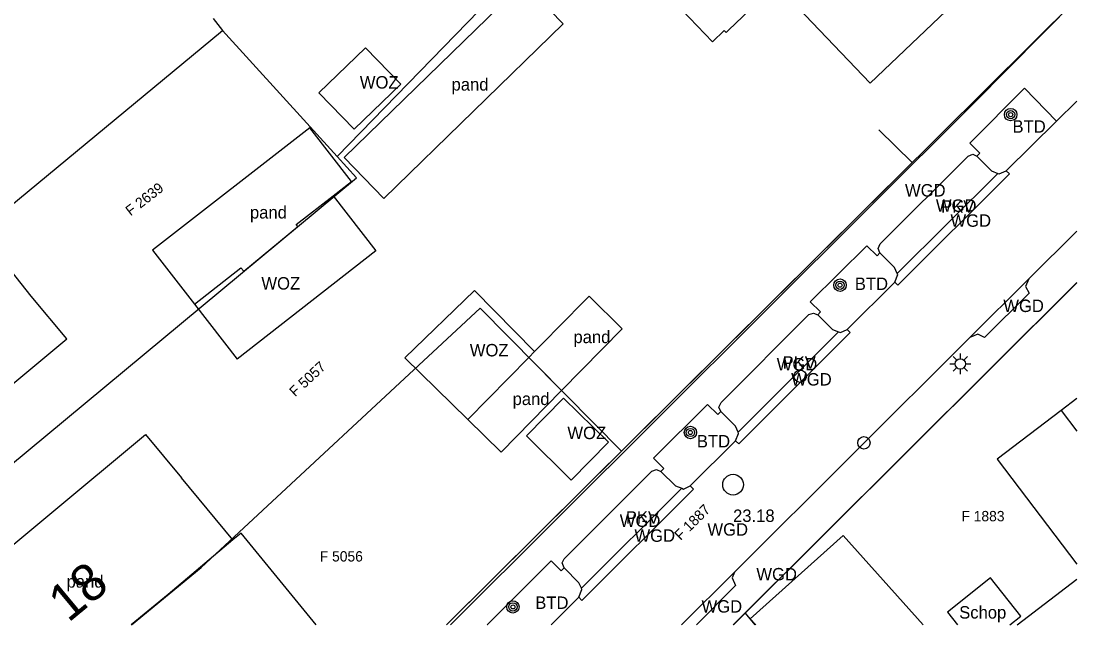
# Model space of a CAD drawing. Extents: x 198240 to 198429, y 356553 to 356721.
# Drawn here: x 198378.2 to 198429.3, y 356553.7 to 356582.9 of the extents above; entities that cross this region are included whole.
import ezdxf

# ---------------------------------------------------------------- set-up
doc = ezdxf.new("R2010")
doc.units = 0
for name, color, linetype in [('begroeid terreindeel kenmerkpunt', 7, 'Continuous'), ('bijgebouw', 7, 'Continuous'), ('BOOM', 7, 'Continuous'), ('Grens maaiveld', 7, 'Continuous'), ('grens WOZ object', 7, 'Continuous'), ('hoofdgebouw', 7, 'Continuous'), ('Hoogtepunt', 7, 'Continuous'), ('huisnummerreeks BGT', 7, 'Continuous'), ('identificerend kenmerkpunt bijpand', 7, 'Continuous'), ('identificerend kenmerkpunt pand', 7, 'Continuous'), ('identificerend kenmerkpunt parkeervak', 7, 'Continuous'), ('identificerend kenmerkpunt WOZ object', 7, 'Continuous'), ('Inspectieput_rioolput', 7, 'Continuous'), ('kant verharding', 7, 'Continuous'), ('kolk', 7, 'Continuous'), ('LICHTMAST', 7, 'Continuous'), ('Perceelnummer', 7, 'Continuous'), ('perceelsgrens_definitief', 7, 'Continuous'), ('schutting geen IMGeo', 7, 'Continuous'), ('tussenmuur', 7, 'Continuous'), ('tussenmuur bijgebouw (GBKN Zuid)', 7, 'Continuous'), ('wegdeel kenmerkpunt', 7, 'Continuous'), ('weginrichtingselement lijn', 7, 'Continuous')]:
    doc.layers.add(name, color=color, linetype=linetype)

msp = doc.modelspace()

# ---------------------------------------------------------------- linework, layer by layer
at = {"layer": 'bijgebouw'}
for p, q in [((198395.764, 356574.305), (198404.433, 356582.738)), ((198395.764, 356574.305), (198393.844, 356576.278)), ((198388.999, 356570.783), (198391.604, 356572.945)), ((198403.387, 356567.24), (198405.417, 356569.305)), ((198403.054, 356566.902), (198402.775, 356566.618)), ((198403.387, 356567.24), (198403.054, 356566.902)), ((198402.775, 356566.618), (198399.823, 356563.617)), ((198429.251, 356564.637), (198428.489, 356564.058)), ((198413.472, 356553.991), (198413.732, 356553.702))]:
    msp.add_line(p, q, dxfattribs=at)
for points in [[(198404.433, 356582.738), (198402.513, 356584.711), (198393.844, 356576.278)], [(198393.313, 356574.422), (198394.212, 356575.122), (198392.188, 356577.719), (198384.587, 356571.795), (198386.611, 356569.198)], [(198391.604, 356572.945), (198391.534, 356573.035), (198393.313, 356574.422)], [(198386.611, 356569.198), (198388.865, 356570.955), (198388.999, 356570.783)], [(198404.358, 356565.019), (198407.286, 356567.997), (198405.682, 356569.574), (198405.417, 356569.305)], [(198399.823, 356563.617), (198401.428, 356562.039), (198404.358, 356565.019)], [(198413.472, 356553.991), (198417.952, 356558.012), (198421.83, 356553.702)]]:
    msp.add_lwpolyline(points, dxfattribs=at)
at = {"layer": 'BOOM'}
for centre, radius in [((198426.05, 356578.35), 0.3), ((198426.05, 356578.35), 0.2), ((198426.05, 356578.35), 0.1), ((198417.807, 356570.11), 0.3), ((198417.807, 356570.11), 0.2), ((198417.807, 356570.11), 0.1), ((198410.579, 356562.994), 0.3), ((198410.579, 356562.994), 0.2), ((198410.579, 356562.994), 0.1), ((198402.003, 356554.569), 0.3), ((198402.003, 356554.569), 0.2), ((198402.003, 356554.569), 0.1)]:
    msp.add_circle(centre, radius, dxfattribs=at)
at = {"layer": 'Grens maaiveld'}
for points in [[(198425.837, 356575.632), (198425.998, 356575.484), (198420.594, 356570.105), (198420.453, 356570.259)], [(198418.147, 356567.967), (198418.298, 356567.827), (198412.917, 356562.449), (198412.763, 356562.594)], [(198410.57, 356560.418), (198410.729, 356560.263), (198405.339, 356554.884), (198405.183, 356555.039)]]:
    msp.add_lwpolyline(points, dxfattribs=at)
at = {"layer": 'grens WOZ object'}
for p, q in [((198412.437, 356582.444), (198414.721, 356584.63)), ((198412.308, 356582.321), (198412.437, 356582.444)), ((198392.632, 356579.397), (198394.874, 356581.576)), ((198394.874, 356581.576), (198396.58, 356579.821)), ((198396.58, 356579.821), (198394.337, 356577.642)), ((198394.337, 356577.642), (198392.632, 356579.397)), ((198393.313, 356574.422), (198395.384, 356571.765)), ((198395.384, 356571.765), (198388.682, 356566.541)), ((198386.611, 356569.198), (198388.682, 356566.541)), ((198402.654, 356562.826), (198404.448, 356564.652)), ((198404.448, 356564.652), (198406.615, 356562.525)), ((198428.489, 356564.058), (198425.397, 356561.71)), ((198404.821, 356560.698), (198402.654, 356562.826)), ((198406.615, 356562.525), (198404.821, 356560.698)), ((198425.397, 356561.71), (198429.251, 356556.635)), ((198425.07, 356555.97), (198422.994, 356554.321)), ((198426.541, 356554.119), (198425.07, 356555.97)), ((198422.994, 356554.321), (198423.486, 356553.702)), ((198426.015, 356553.702), (198426.541, 356554.119))]:
    msp.add_line(p, q, dxfattribs=at)
for points in [[(198409.054, 356584.582), (198411.65, 356581.864), (198412.216, 356582.419), (198412.308, 356582.321)], [(198399.823, 356563.617), (198396.784, 356566.605), (198400.147, 356569.847), (198403.054, 356566.902)]]:
    msp.add_lwpolyline(points, dxfattribs=at)
at = {"layer": 'hoofdgebouw'}
for p, q in [((198378.73, 356569.587), (198376.341, 356572.579)), ((198428.489, 356564.058), (198429.251, 356563.054)), ((198388.477, 356557.806), (198385.996, 356560.798)), ((198388.866, 356558.133), (198388.477, 356557.806)), ((198392.493, 356553.702), (198388.866, 356558.133))]:
    msp.add_line(p, q, dxfattribs=at)
for points in [[(198414.721, 356584.63), (198419.264, 356579.863), (198424.933, 356585.283), (198420.379, 356590.045)], [(198366.989, 356565.052), (198371.275, 356559.894), (198380.45, 356567.516), (198378.73, 356569.587)], [(198376.395, 356553.702), (198375.087, 356555.277), (198384.259, 356562.891), (198385.996, 356560.798)]]:
    msp.add_lwpolyline(points, dxfattribs=at)
at = {"layer": 'Inspectieput_rioolput'}
msp.add_circle((198412.64, 356560.475), 0.5, dxfattribs=at)
at = {"layer": 'kant verharding'}
for p, q in [((198429.251, 356579.007), (198428.27, 356578.036)), ((198428.27, 356578.036), (198425.837, 356575.632)), ((198425.439, 356575.511), (198420.571, 356570.681)), ((198426.927, 356570.413), (198429.251, 356572.726)), ((198420.453, 356570.259), (198418.147, 356567.967)), ((198424.082, 356567.58), (198426.927, 356570.413)), ((198412.701, 356556.251), (198424.082, 356567.58)), ((198417.74, 356567.85), (198412.879, 356563.007)), ((198412.763, 356562.594), (198410.57, 356560.418)), ((198410.159, 356560.299), (198405.309, 356555.468)), ((198410.141, 356553.702), (198412.701, 356556.251)), ((198405.183, 356555.039), (198403.853, 356553.702))]:
    msp.add_line(p, q, dxfattribs=at)
for points in [[(198398.992, 356553.702), (198424.254, 356578.89), (198429.251, 356583.945)], [(198424.425, 356576.339), (198424.557, 356576.486), (198424.073, 356576.971), (198426.726, 356579.628), (198428.27, 356578.036)], [(198419.733, 356571.666), (198419.644, 356571.89), (198419.746, 356572.106), (198423.996, 356576.347), (198424.216, 356576.432), (198424.425, 356576.339)], [(198424.425, 356576.339), (198425.132, 356575.627), (198425.439, 356575.511)], [(198425.439, 356575.511), (198425.497, 356575.489), (198425.837, 356575.632)], [(198416.742, 356568.674), (198416.867, 356568.816), (198416.364, 356569.3), (198419.103, 356572.011), (198419.595, 356571.523), (198419.733, 356571.666)], [(198420.571, 356570.681), (198420.443, 356570.957), (198419.733, 356571.666)], [(198420.453, 356570.259), (198420.6, 356570.62), (198420.571, 356570.681)], [(198429.251, 356570.243), (198412.651, 356553.702)], [(198426.927, 356570.413), (198426.77, 356570.053), (198426.944, 356569.719), (198424.794, 356567.578), (198424.461, 356567.74), (198424.082, 356567.58)], [(198412.041, 356564.01), (198411.949, 356564.218), (198412.058, 356564.437), (198416.304, 356568.693), (198416.533, 356568.76), (198416.742, 356568.674)], [(198416.742, 356568.674), (198417.438, 356567.97), (198417.74, 356567.85)], [(198417.74, 356567.85), (198417.823, 356567.817), (198418.147, 356567.967)], [(198409.156, 356561.117), (198409.295, 356561.258), (198408.798, 356561.748), (198411.411, 356564.354), (198411.906, 356563.862), (198412.041, 356564.01)], [(198412.879, 356563.007), (198412.753, 356563.297), (198412.041, 356564.01)], [(198412.763, 356562.594), (198412.902, 356562.953), (198412.879, 356563.007)], [(198404.476, 356556.453), (198404.376, 356556.694), (198404.476, 356556.893), (198408.722, 356561.12), (198408.943, 356561.208), (198409.156, 356561.117)], [(198409.156, 356561.117), (198409.864, 356560.416), (198410.159, 356560.299)], [(198410.159, 356560.299), (198410.243, 356560.265), (198410.57, 356560.418)], [(198400.773, 356553.702), (198400.765, 356553.71), (198403.845, 356556.802), (198404.33, 356556.317), (198404.476, 356556.453)], [(198405.309, 356555.468), (198405.181, 356555.738), (198404.476, 356556.453)], [(198412.701, 356556.251), (198412.598, 356555.967), (198412.752, 356555.597), (198410.866, 356553.702)], [(198405.183, 356555.039), (198405.333, 356555.417), (198405.309, 356555.468)]]:
    msp.add_lwpolyline(points, dxfattribs=at)
at = {"layer": 'kolk'}
for centre in [(198415.882, 356565.713), (198418.963, 356562.494)]:
    msp.add_circle(centre, 0.3, dxfattribs=at)
at = {"layer": 'LICHTMAST'}
for p, q in [((198423.443, 356566.485), (198423.266, 356566.662)), ((198423.62, 356566.558), (198423.62, 356566.808)), ((198423.797, 356566.485), (198423.974, 356566.662)), ((198423.12, 356566.308), (198423.37, 356566.308)), ((198423.266, 356565.954), (198423.443, 356566.131)), ((198423.62, 356565.808), (198423.62, 356566.058)), ((198423.974, 356565.954), (198423.797, 356566.131)), ((198423.87, 356566.308), (198424.12, 356566.308))]:
    msp.add_line(p, q, dxfattribs=at)
msp.add_circle((198423.62, 356566.308), 0.25, dxfattribs=at)
at = {"layer": 'perceelsgrens_definitief'}
for points in [[(198393.504, 356576.321), (198416.379, 356599.858)], [(198407.251, 356562.099), (198429.251, 356583.95)], [(198387.513, 356582.994), (198387.979, 356582.417)], [(198363.947, 356562.536), (198387.979, 356582.417)], [(198387.979, 356582.417), (198393.504, 356576.321)], [(198370.106, 356555.109), (198394.44, 356575.297), (198393.504, 356576.321)], [(198413.226, 356554.261), (198429.251, 356570.222)], [(198383.576, 356553.702), (198386.936, 356556.466), (198400.413, 356569.003)], [(198407.251, 356562.099), (198400.413, 356569.003)], [(198398.796, 356553.702), (198407.251, 356562.099)], [(198426.362, 356553.702), (198429.251, 356555.904)], [(198412.664, 356553.702), (198413.226, 356554.261)], [(198413.226, 356554.261), (198413.685, 356553.702)]]:
    msp.add_lwpolyline(points, dxfattribs=at)
at = {"layer": 'schutting geen IMGeo'}
msp.add_lwpolyline([(198398.791, 356553.702), (198421.29, 356576.042), (198419.689, 356577.618)], dxfattribs=at)
at = {"layer": 'tussenmuur'}
for p, q in [((198388.477, 356557.806), (198385.349, 356555.177)), ((198385.349, 356555.177), (198383.564, 356553.702))]:
    msp.add_line(p, q, dxfattribs=at)
at = {"layer": 'tussenmuur bijgebouw (GBKN Zuid)'}
msp.add_line((198402.775, 356566.618), (198404.358, 356565.019), dxfattribs=at)
at = {"layer": 'weginrichtingselement lijn'}
for points in [[(198425.837, 356575.632), (198425.998, 356575.484), (198420.594, 356570.105), (198420.453, 356570.259)], [(198418.147, 356567.967), (198418.298, 356567.827), (198412.917, 356562.449), (198412.763, 356562.594)], [(198410.57, 356560.418), (198410.729, 356560.263), (198405.339, 356554.884), (198405.183, 356555.039)]]:
    msp.add_lwpolyline(points, dxfattribs=at)

# ---------------------------------------------------------------- texts
at = {"layer": 'begroeid terreindeel kenmerkpunt'}
for p in [(198426.14, 356577.477), (198418.522, 356569.879), (198410.891, 356562.273), (198403.083, 356554.474)]:
    msp.add_text('BTD', height=0.6, dxfattribs=at).set_placement(p)
at = {"layer": 'Hoogtepunt'}
msp.add_text('23.18', height=0.6, dxfattribs=at).set_placement((198412.64, 356558.675))
msp.add_text('23.18', height=0.6, dxfattribs=at).set_placement((198412.64, 356558.675))
at = {"layer": 'huisnummerreeks BGT'}
msp.add_text('18', height=1.8, rotation=39.7, dxfattribs=at).set_placement((198380.524, 356553.78))
at = {"layer": 'identificerend kenmerkpunt bijpand'}
for p in [(198399.038, 356579.51), (198389.298, 356573.33), (198404.928, 356567.31), (198401.988, 356564.32)]:
    msp.add_text('pand', height=0.6, dxfattribs=at).set_placement(p)
at = {"layer": 'identificerend kenmerkpunt pand'}
msp.add_text('pand', height=0.6, dxfattribs=at).set_placement((198380.438, 356555.5))
at = {"layer": 'identificerend kenmerkpunt parkeervak'}
for p in [(198422.692, 356573.617), (198415.034, 356566.074), (198407.459, 356558.59)]:
    msp.add_text('PKV', height=0.6, dxfattribs=at).set_placement(p)
at = {"layer": 'identificerend kenmerkpunt WOZ object'}
for s, p in [('WOZ', (198394.606, 356579.609)), ('WOZ', (198389.851, 356569.9)), ('WOZ', (198399.919, 356566.671)), ('WOZ', (198404.635, 356562.675)), ('Schop', (198423.565, 356554.006))]:
    msp.add_text(s, height=0.6, dxfattribs=at).set_placement(p)
at = {"layer": 'Perceelnummer'}
for s, rotation, p in [('F 2639', 37.9, (198383.531, 356573.432)), ('F 5057', 42.9, (198391.483, 356564.69)), ('F 1887', 44.8, (198410.104, 356557.753))]:
    msp.add_text(s, height=0.5, rotation=rotation, dxfattribs=at).set_placement(p)
for s, p in [('F 1883', (198423.673, 356558.705)), ('F 5056', (198392.671, 356556.762))]:
    msp.add_text(s, height=0.5, dxfattribs=at).set_placement(p)
at = {"layer": 'wegdeel kenmerkpunt'}
for p in [(198420.947, 356574.392), (198422.439, 356573.654), (198423.144, 356572.932), (198425.696, 356568.813), (198414.748, 356565.991), (198415.445, 356565.263), (198407.166, 356558.435), (198407.876, 356557.714), (198411.402, 356558.011), (198413.765, 356555.85), (198411.117, 356554.294)]:
    msp.add_text('WGD', height=0.6, dxfattribs=at).set_placement(p)

doc.saveas('drawing.dxf')
